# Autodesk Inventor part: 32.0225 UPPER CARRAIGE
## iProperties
Created: 2012-10
Part Number: 32.0225 UPPER CARRAIGE
Document SubType Name: Modeling
Designer: Administrator
Density: 1.4 g/cm^3
Material: PVC-Piping
Mass: 56.2422 g
Surface Area: 180.831 cm^2
Volume: 40.173 cm^3
Author: Administrator
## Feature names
1. Base1
